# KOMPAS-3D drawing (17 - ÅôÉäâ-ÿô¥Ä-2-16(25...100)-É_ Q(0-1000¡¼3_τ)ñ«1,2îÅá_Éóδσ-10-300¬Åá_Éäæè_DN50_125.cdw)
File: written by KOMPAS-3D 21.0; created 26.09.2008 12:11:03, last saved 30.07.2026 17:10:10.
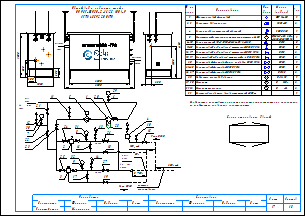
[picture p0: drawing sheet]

Sheets 1-2: A3, landscape

Document properties: Наименование: Макро:21; Автор: RaskoAdmin; Форматы листов документа: 2xA3; Полное имя файла: \\ur38nt01\Departments\КТО\КБ ПУРДГ\Заявки\Прайс-лист на типовые шкафы ГРПШ\ПУРДГ_стандарт_30_04_2026\ПУРДГ с РДСК\ПУРДГ-ШУЭО-2-16(25...100)-Р_ Q(0-1000нм3_ч)до1,2МПа_Рвых-10-300кПа_РДСК_DN50_125.cdw

Title block, sheet 1: Наименование: Пункт учета газа / ПУГ-Ш-400-Р / ЛГТИ.485922.001ТУ; designation: ЛГТИ.03.4411141; sheet number: 1; Количество листов документа: 2; organisation: ООО "ЭЛЬСТЕР Газэлектроника"; Форматы листов документа: A3; stored path: C:\Рабочие документы\Компас\ПУГ\Схема.cdw; Разработал: Устинов; Проверил: Кошкин; Утвердил: Кошкин
Title block, sheet 2: sheet number: 2; stored path: D:\Рабочие документы\Заявки\ПУРДГ\ПУРДГ-ШУЭО-2-100-Р 4411220.cdw; designation, second copy: ЛГТИ.03.4411141-

Views: Вид 1, Вид 2
Referenced files: wcvoit.frw
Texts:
  Normal
  № на
  схеме
  Усл.
  обозн.
  Марка
  (модель)
  Кол.
  Фильтр газовый фланцевый
  ФГ 16-50
  Регулятор давления газа
  РДСК-50
  Клапан предохранительный сбросной
  КПС DN20
  Измерительный комплекс с ротационным счетчиком Ду50
  СГ-ЭК-Р-(0,2...2,0)-
  Кран кнопочный VE-РАСКО-НЗ-1,6-G1/2-М20
  DN15
  Кран шаровой "под приварку" штуцерный DN20 PN16
  DN20
  Кран шаровой "под приварку" штуцерный DN15 PN16
  Кран шаровой "под приварку" штуцерный п/п DN20 PN16
  Кран шаровой фланцевый с мех. приводом DN50 PN16
  Кран шаровой фланцевый DN50 PN16
  Кран шаровой фланцевый DN125 PN16
  DN50
  DN125
  Индикатор перепада давления
  Манометр
  Манометр-напоромер
  Электрообогреватель взрывозащищенный 400Вт
  Delta 15
  0...     МПа
  0...     кПа
  Общий вид и габариты шкафа
  ПУРДГ-ШУЭО-2-16(25...100)-Р
  Выход газа
  Вход газа
  logo-rasko-ge.png
  DN 1
  местное
  сопротивление
  Римп DN20
  Выход
  газа
  Р=     кПа
  Вход
  Р=       МПа
  PDI
  Схема открывания дверей
  Предприятие изготовитель может заменять комплектующие на аналогичные,
  не ухудшающие заявленных характеристик.
  Должность
  Конструктор
  Фамилия
  Подпись
  Дата
  Согласовано
  Максимкин
  Лист
  Листов
  POLYLINE_STYLE_0.18_RGB_0_0_0
  POLYLINE_STYLE_0.50_RGB_0_0_0
  POLYLINE_STYLE_0.34_RGB_0_0_0
  PHANTOM_RGB_0_0_0_SC_1_THICK_0.18
  K5LT_THIN_RGB_0_0_0_THICK_0.18
  K5LT32769_RGB_0_0_0_THICK_0.18
  K5LT12_RGB_0_0_0_SC_1_THICK_0.18
  K5LT_DASHED_RGB_0_0_0_SC_1_THICK_0.18
  ACISOTGL_RGB_0_0_0_SC_0.8_THICK_0.25
  CONTINUOUS_RGB_0_127_31_THICK_0.3
  CONTINUOUS_RGB_0_0_255_THICK_0.35
  CONTINUOUS_RGB_255_0_0_THICK_0.35
  POLYLINE_STYLE_0.25_RGB_0_0_0
  CONTINUOUS_RGB_0_0_0_THICK_0.5
  POLYLINE_STYLE_0.35_RGB_0_0_255
  CONTINUOUS_RGB_0_0_0_THICK_0.4
  CONTINUOUS_RGB_0_0_0_THICK_0.35
  НЕВИДИМАЯ_RGB_0_0_0_SC_0.3_THICK_0.25
  СONTINUOUS_RGB_0_0_0_THICK_0.25
  ОСЕВАЯ2_RGB_248_153_30_SC_0.3_THICK_0.25
  Без оформления
Dimensions and other numbers on the sheet: 1; 2, 3; 2; 4; 5; 6-10; 11-15; 16, 17; 18, 19; 20; 21-25; 26, 27; 28; 29, 30; 31, 32; 33; 1500; 250; 300; 1050; 550; 305; 2500; 4130; 2000; 2800; 5,,,7DN 1; 7; 30; 12; 21; 22; 23; 11; 6; 29; 24; 31; 8; 16; 13; 26; 18; 10; 15; 25; 32; 9; 3; 17; 14; 27; 19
